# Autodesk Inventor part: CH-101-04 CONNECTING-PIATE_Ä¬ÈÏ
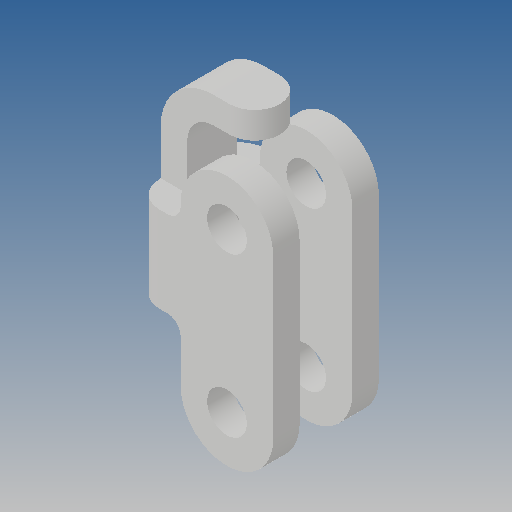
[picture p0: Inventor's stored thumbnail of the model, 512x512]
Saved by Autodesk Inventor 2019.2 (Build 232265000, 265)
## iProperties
Created: 2010-06
Part Number: CH-101-04 CONNECTING-PIATE_Ä¬ÈÏ
Material: Ogólny
Document SubType Name: Modeling
Designer: CADENGINEERING4
Density: 1 g/cm^3
Appearance: Domyślna
Author: CADENGINEERING4
Revision Number: ÈÎºÎ
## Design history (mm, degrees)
feature "NONE"
node "Bryła1"
